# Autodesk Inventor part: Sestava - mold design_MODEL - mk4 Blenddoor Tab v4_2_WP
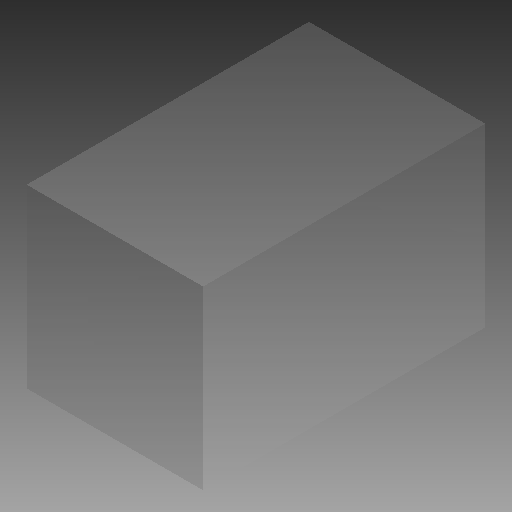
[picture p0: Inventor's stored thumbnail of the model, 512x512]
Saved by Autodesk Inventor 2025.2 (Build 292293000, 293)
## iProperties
Part Number: Sestava - mold design_MODEL - mk4 Blenddoor Tab v4_2_WP
Material: Generický
Document SubType Name: Modelování
Designer: Patrik
Density: 1 g/cm^3
Appearance: Výchozí
d1: 2,250 cm
d2: 2,250 cm
d3: 2,250 cm
d4: 2,250 cm
d5: 7,200 cm
d6: 0,0 deg
Xmin: -22,500 mm
Ymin: -22,500 mm
Zmin: -36,000 mm
Xmax: 22,500 mm
Ymax: 22,500 mm
Zmax: 36,000 mm
Author: Patrik
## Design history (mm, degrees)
sketch "Náčrt1"
  geometry: L1 (-19.871, 29.263)-(25.129, 29.263); L2 (25.129, 29.263)-(25.129, -15.737); L3 (25.129, -15.737)-(-19.871, -15.737); L4 (-19.871, -15.737)-(-19.871, 29.263); 1 further point
  constraints: 8 end point, 2 parallel, 1 horizontal, 1 perpendicular, 1 other
  dimensions: "d1" = 22.5 distance from line of L4 point (2.629, 6.763) (= -Xmin); "d2" = 22.5 distance from line of L2 point (2.629, 6.763) (= Xmax); "d3" = 22.5 distance from line of L3 point (2.629, 6.763) (= -Ymin); "d4" = 22.5 distance from line of L1 point (2.629, 6.763) (= Ymax)
extrude "Vysunutí1" join sketch "Náčrt1" distance "d5" = 72 (= Zmax - Zmin); taper "d6" = 0 deg
node "Těleso1"
node "Objemová tělesa"
node "Povrchová tělesa"
other parameters: "Xmin" = -22.5 [user parameter; used in 1 equation term], "Ymin" = -22.5 [user parameter; used in 1 equation term], "Zmin" = -36 [user parameter; used in 1 equation term], "Xmax" = 22.5 [user parameter; used in 1 equation term], "Ymax" = 22.5 [user parameter; used in 1 equation term], "Zmax" = 36 [user parameter; used in 1 equation term], "d23" = -39.77246
